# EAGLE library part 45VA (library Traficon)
TRANSFORMER 1 primary windig + 1 primary winding with tap, 2 secondary windings, core ring
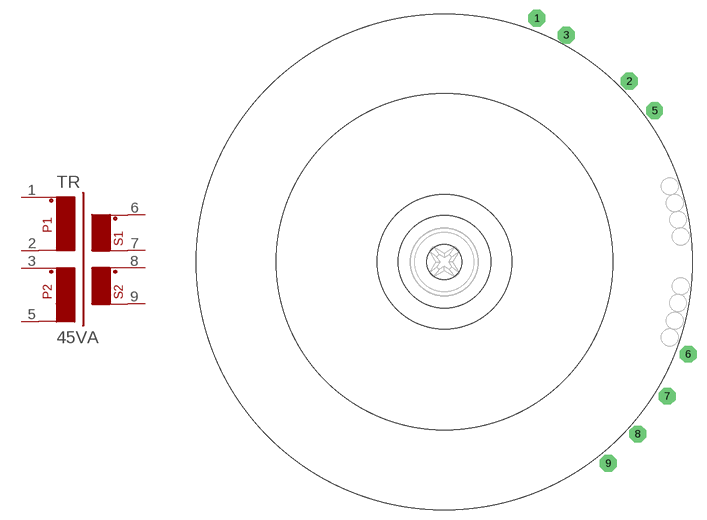
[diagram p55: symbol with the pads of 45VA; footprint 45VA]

Designator prefix TR

## 45VA  [45VA]
1  1  pas
2  2  pas
3  3  pas
5  5  pas
6  6  pas
7  7  pas
8  8  pas
9  9  pas

## Footprint 45VA (pad centres in mm)
TRANSFORMER 1 primary windig + 1 primary winding with tap, 2 secondary windings, core ring
drill 1.6 pad 2.54 octagon: 1 13.97,36.83; 2 27.94,27.305; 3 18.415,34.29; 5 31.75,22.86
drill 1.016 pad 2.54 octagon: 6 36.83,-13.97; 7 33.655,-20.32; 8 29.21,-26.035; 9 24.765,-30.48
hole 5.309 at 0,0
